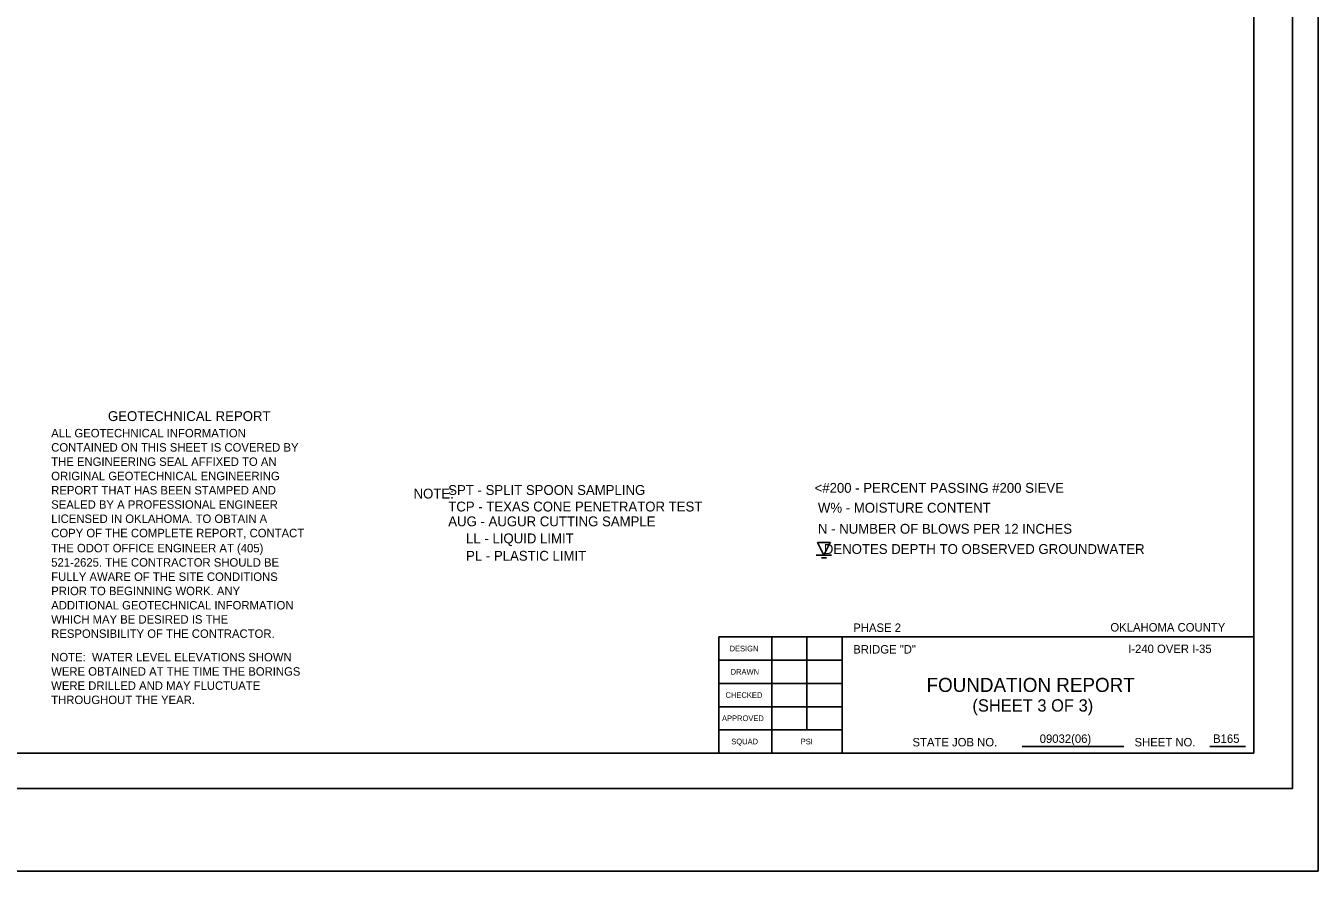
# Model space of a CAD drawing. Extents: x -93 to 177, y 25 to 84.
# Drawn here: x 8.45 to 26.81, y 25.37 to 37.37 of the extents above; entities that cross this region are included whole.
import ezdxf

# ---------------------------------------------------------------- set-up
doc = ezdxf.new("R2010")
doc.units = 0
for name, color, linetype in [('SHT_Plot_Shape_Full', 7, 'Continuous'), ('SHT_Plot_Shape_Half', 7, 'Continuous'), ('SHT_Sheet_Border', 7, 'Continuous'), ('SHT_Standard_Sheet_Lines', 7, 'Continuous'), ('SHT_Standard_Sheet_Txt', 7, 'Continuous'), ('T-Subtitle', 7, 'Continuous'), ('T-Title', 7, 'Continuous'), ('Text', 7, 'Continuous')]:
    doc.layers.add(name, color=color, linetype=linetype)

# ---------------------------------------------------------------- blocks, each defined once
blk = doc.blocks.new('DGRFC_WTLEV1')
for points in [[(-0.0127, 0), (0.0127, 0)], [(0, 0), (0.0106, 0.0212), (-0.0106, 0.0212), (0, 0)], [(-0.0042, -0.0042), (0.0042, -0.0042)]]:
    blk.add_lwpolyline(points)

msp = doc.modelspace()

# ---------------------------------------------------------------- linework, layer by layer
at = {"layer": 'SHT_Plot_Shape_Full'}
msp.add_lwpolyline([(-9.19, 49.368), (26.81, 49.368), (26.81, 25.368), (-9.19, 25.368)], close=True, dxfattribs=at)
at = {"layer": 'SHT_Plot_Shape_Half'}
msp.add_lwpolyline([(-7.552, 48.543), (26.448, 48.543), (26.448, 26.543), (-7.552, 26.543)], close=True, dxfattribs=at)
at = {"layer": 'SHT_Sheet_Border'}
for p, q in [((18.298, 27.043), (18.298, 28.693)), ((18.298, 28.693), (25.898, 28.693)), ((20.048, 27.043), (20.048, 28.694))]:
    msp.add_line(p, q, dxfattribs=at)
msp.add_lwpolyline([(25.898, 27.043), (-5.602, 27.043), (-5.602, 48.043), (25.898, 48.043)], close=True, dxfattribs=at)
at = {"layer": 'SHT_Standard_Sheet_Lines'}
for p, q in [((19.048, 27.043), (19.048, 28.694)), ((19.548, 27.373), (19.548, 28.694)), ((22.608, 27.139), (24.049, 27.139)), ((25.273, 27.139), (25.776, 27.139))]:
    msp.add_line(p, q, dxfattribs=at)
for points in [[(20.048, 28.363), (18.298, 28.363)], [(20.048, 28.033), (18.298, 28.033)], [(20.048, 27.703), (18.298, 27.703)], [(20.048, 27.373), (18.298, 27.373)]]:
    msp.add_lwpolyline(points, dxfattribs=at)

# ---------------------------------------------------------------- block references
at = {"xscale": 8.503919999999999, "yscale": 8.503919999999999}
msp.add_blockref('DGRFC_WTLEV1', (19.789, 29.853), dxfattribs=at)

# ---------------------------------------------------------------- texts
at = {"layer": 'SHT_Standard_Sheet_Txt'}
for s, height, p in [('PHASE 2', 0.12, (20.207, 28.764)), ('OKLAHOMA COUNTY', 0.12, (23.859, 28.77)), ('DESIGN', 0.08, (18.45, 28.488)), ('BRIDGE "D" ', 0.12, (20.207, 28.457)), ('I-240 OVER I-35', 0.12, (24.111, 28.464)), ('DRAWN', 0.08, (18.465, 28.158)), ('CHECKED', 0.08, (18.392, 27.828)), ('APPROVED', 0.08, (18.342, 27.498)), ('SQUAD', 0.08, (18.474, 27.168)), ('PSI', 0.08, (19.46, 27.168)), ('STATE JOB NO.', 0.12, (21.048, 27.139)), ('09032(06)', 0.12, (22.855, 27.189)), ('SHEET NO. ', 0.12, (24.202, 27.139)), ('B165', 0.12, (25.318, 27.189))]:
    msp.add_text(s, height=height, dxfattribs=at).set_placement(p)
at = {"layer": 'T-Subtitle'}
msp.add_text('(SHEET 3 OF 3)', height=0.175, dxfattribs=at).set_placement((21.899, 27.633))
at = {"layer": 'T-Title'}
msp.add_text('FOUNDATION REPORT', height=0.2, dxfattribs=at).set_placement((21.248, 27.912))
at = {"layer": 'Text'}
for s, height, p in [('GEOTECHNICAL REPORT', 0.14, (9.62, 31.758)), ('ALL GEOTECHNICAL INFORMATION ', 0.12, (8.814, 31.526)), ('CONTAINED ON THIS SHEET IS COVERED BY ', 0.12, (8.814, 31.324)), ('THE ENGINEERING SEAL AFFIXED TO AN ', 0.12, (8.814, 31.121)), ('ORIGINAL GEOTECHNICAL ENGINEERING ', 0.12, (8.814, 30.918)), ('    SPT - SPLIT SPOON SAMPLING', 0.14, (14.246, 30.709)), (' <#200 - PERCENT PASSING #200 SIEVE', 0.14, (19.605, 30.739)), ('REPORT THAT HAS BEEN STAMPED AND ', 0.12, (8.814, 30.716)), ('NOTE:', 0.14, (13.961, 30.658)), ('SEALED BY A PROFESSIONAL ENGINEER ', 0.12, (8.814, 30.513)), ('    TCP - TEXAS CONE PENETRATOR TEST', 0.14, (14.246, 30.474)), ('W% - MOISTURE CONTENT', 0.14, (19.705, 30.457)), ('LICENSED IN OKLAHOMA. TO OBTAIN A ', 0.12, (8.814, 30.311)), ('    AUG - AUGUR CUTTING SAMPLE', 0.14, (14.246, 30.264)), ('N - NUMBER OF BLOWS PER 12 INCHES', 0.14, (19.705, 30.158)), ('COPY OF THE COMPLETE REPORT, CONTACT ', 0.12, (8.814, 30.108)), (' LL - LIQUID LIMIT', 0.14, (14.655, 30.022)), ('THE ODOT OFFICE ENGINEER AT (405) ', 0.12, (8.814, 29.894)), ('    DENOTES DEPTH TO OBSERVED GROUNDWATER', 0.14, (19.581, 29.871)), ('521-2625. THE CONTRACTOR SHOULD BE ', 0.12, (8.814, 29.691)), (' PL - PLASTIC LIMIT', 0.14, (14.655, 29.775)), ('FULLY AWARE OF THE SITE CONDITIONS ', 0.12, (8.814, 29.488)), ('PRIOR TO BEGINNING WORK. ANY ', 0.12, (8.814, 29.286)), ('ADDITIONAL GEOTECHNICAL INFORMATION ', 0.12, (8.814, 29.083)), ('WHICH MAY BE DESIRED IS THE ', 0.12, (8.814, 28.882)), ('RESPONSIBILITY OF THE CONTRACTOR.', 0.12, (8.814, 28.68)), ('NOTE:  WATER LEVEL ELEVATIONS SHOWN ', 0.12, (8.814, 28.346)), ('WERE OBTAINED AT THE TIME THE BORINGS ', 0.12, (8.814, 28.143)), ('WERE DRILLED AND MAY FLUCTUATE ', 0.12, (8.814, 27.942)), ('THROUGHOUT THE YEAR.', 0.12, (8.814, 27.74))]:
    msp.add_text(s, height=height, dxfattribs=at).set_placement(p)

doc.saveas('drawing.dxf')
